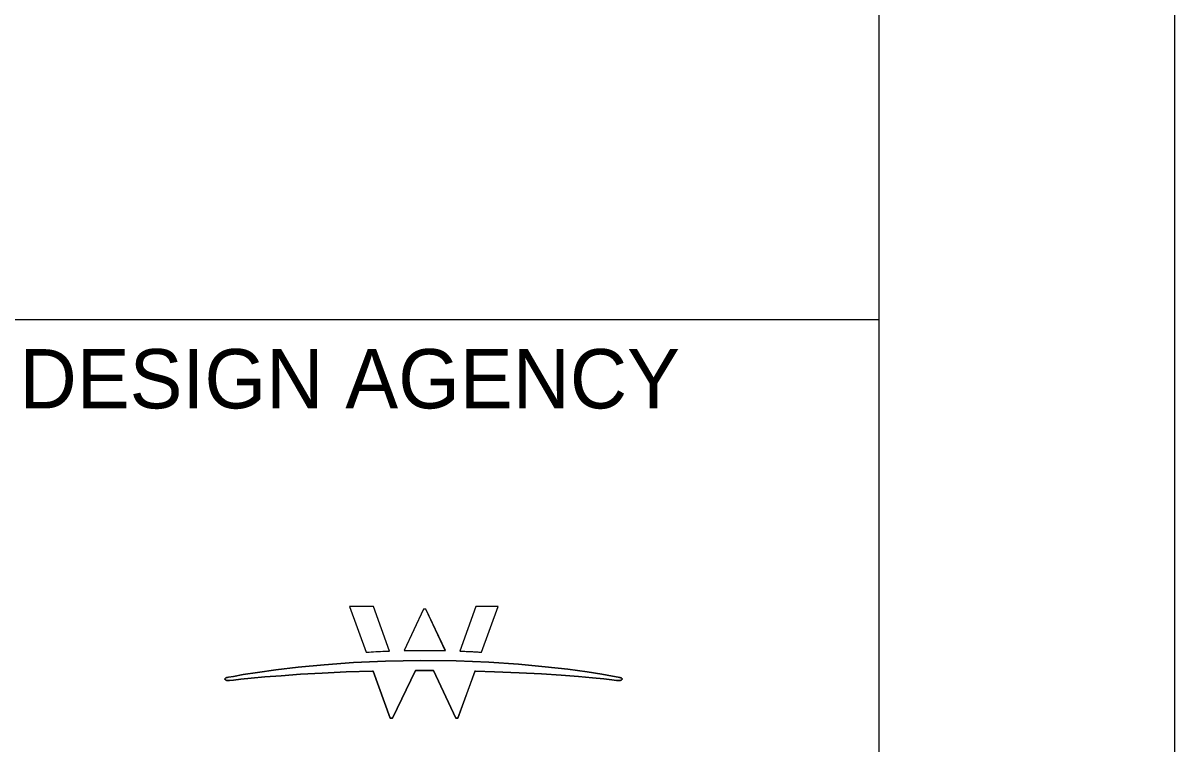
# Model space of a CAD drawing. Extents: x 0 to 1381193, y -3 to 468856.
# Drawn here: x 32.056 to 34, y 3.784 to 5 of the extents above; entities that cross this region are included whole.
import ezdxf

# ---------------------------------------------------------------- set-up
doc = ezdxf.new("R2010")
doc.units = 0
for name, color, linetype in [('SV_P_Mon_Cells_Set', 7, 'Continuous'), ('SV_X_Mon_Cells_Found', 7, 'Continuous'), ('SV_X_Shot_Marker', 7, 'Continuous')]:
    doc.layers.add(name, color=color, linetype=linetype)

msp = doc.modelspace()

# ---------------------------------------------------------------- linework, layer by layer
at = {"layer": 'SV_P_Mon_Cells_Set'}
msp.add_lwpolyline([(0, 0), (34, 0), (34, 22), (0, 22)], close=True, dxfattribs=at)
at = {"layer": 'SV_X_Mon_Cells_Found'}
msp.add_line((32, 4.5), (33.5, 4.5), dxfattribs=at)
msp.add_lwpolyline([(1.5, 21.5), (33.5, 21.5), (33.5, 0.5), (1.5, 0.5)], close=True, dxfattribs=at)
at = {"layer": 'SV_X_Shot_Marker'}
for points in [[(32.6475, 4.0156), (32.607, 4.0156), (32.6351, 3.9388), (32.6398, 3.9391), (32.6437, 3.9393), (32.6476, 3.9395), (32.6515, 3.9397), (32.6555, 3.9399), (32.6594, 3.9401), (32.6634, 3.9403), (32.6674, 3.9404), (32.6715, 3.9406), (32.6746, 3.9407)], [(32.7356, 4.0111), (32.7318, 4.0111), (32.6991, 3.9414), (32.6993, 3.9414), (32.701, 3.9415), (32.7028, 3.9415), (32.7045, 3.9415), (32.7063, 3.9415), (32.708, 3.9416), (32.7097, 3.9416), (32.7115, 3.9416), (32.7132, 3.9416), (32.715, 3.9417), (32.7168, 3.9417), (32.7185, 3.9417), (32.7203, 3.9417), (32.7221, 3.9417), (32.7239, 3.9417), (32.7256, 3.9417), (32.7274, 3.9418), (32.7292, 3.9418), (32.731, 3.9418), (32.7328, 3.9418), (32.7347, 3.9418), (32.7366, 3.9418), (32.7386, 3.9418), (32.7405, 3.9417), (32.7424, 3.9417), (32.7443, 3.9417), (32.7462, 3.9417), (32.7481, 3.9417), (32.7499, 3.9417), (32.7518, 3.9416), (32.7537, 3.9416), (32.7556, 3.9416), (32.7575, 3.9416), (32.7593, 3.9415), (32.7612, 3.9415), (32.763, 3.9415), (32.7649, 3.9414), (32.7667, 3.9414), (32.7686, 3.9414), (32.7689, 3.9414)], [(32.8202, 4.0156), (32.7933, 3.9406), (32.7943, 3.9406), (32.7961, 3.9405), (32.798, 3.9404), (32.7999, 3.9403), (32.8017, 3.9403), (32.8036, 3.9402), (32.8054, 3.9401), (32.8073, 3.94), (32.8091, 3.9399), (32.8109, 3.9399), (32.8127, 3.9398), (32.8146, 3.9397), (32.8164, 3.9396), (32.8182, 3.9395), (32.82, 3.9394), (32.8218, 3.9393), (32.8236, 3.9392), (32.8254, 3.9391), (32.8271, 3.939), (32.8298, 3.9388), (32.8575, 4.0156)]]:
    msp.add_lwpolyline(points, close=True, dxfattribs=at)
for points in [[(32.6475, 4.0156), (32.607, 4.0156), (32.6351, 3.9388), (32.6398, 3.9391), (32.6437, 3.9393), (32.6476, 3.9395), (32.6515, 3.9397), (32.6555, 3.9399), (32.6594, 3.9401), (32.6634, 3.9403), (32.6674, 3.9404), (32.6715, 3.9406), (32.6746, 3.9407), (32.6475, 4.0156)], [(32.7356, 4.0111), (32.7318, 4.0111), (32.6991, 3.9414), (32.701, 3.9415), (32.7028, 3.9415), (32.7045, 3.9415), (32.7063, 3.9415), (32.708, 3.9416), (32.7097, 3.9416), (32.7115, 3.9416), (32.7132, 3.9416), (32.715, 3.9417), (32.7168, 3.9417), (32.7185, 3.9417), (32.7203, 3.9417), (32.7221, 3.9417), (32.7239, 3.9417), (32.7256, 3.9417), (32.7274, 3.9418), (32.7292, 3.9418), (32.731, 3.9418), (32.7328, 3.9418), (32.7347, 3.9418), (32.7366, 3.9418), (32.7386, 3.9418), (32.7405, 3.9417), (32.7424, 3.9417), (32.7443, 3.9417), (32.7462, 3.9417), (32.7481, 3.9417), (32.7499, 3.9417), (32.7518, 3.9416), (32.7537, 3.9416), (32.7556, 3.9416), (32.7575, 3.9416), (32.7593, 3.9415), (32.7612, 3.9415), (32.763, 3.9415), (32.7649, 3.9414), (32.7667, 3.9414), (32.7686, 3.9414), (32.7356, 4.0111)], [(32.8202, 4.0156), (32.7933, 3.9406), (32.7943, 3.9406), (32.7961, 3.9405), (32.798, 3.9404), (32.7999, 3.9403), (32.8017, 3.9403), (32.8036, 3.9402), (32.8054, 3.9401), (32.8073, 3.94), (32.8091, 3.9399), (32.8109, 3.9399), (32.8127, 3.9398), (32.8146, 3.9397), (32.8164, 3.9396), (32.8182, 3.9395), (32.82, 3.9394), (32.8218, 3.9393), (32.8236, 3.9392), (32.8254, 3.9391), (32.8271, 3.939), (32.8298, 3.9388), (32.8575, 4.0156), (32.8202, 4.0156)], [(32.6457, 3.9069), (32.6012, 3.9055), (32.5605, 3.9036), (32.5239, 3.9015), (32.4915, 3.8992), (32.4638, 3.897), (32.441, 3.8949), (32.4233, 3.8931), (32.411, 3.8918), (32.4045, 3.891), (32.403, 3.8909), (32.402, 3.8909), (32.401, 3.891), (32.4001, 3.8911), (32.3993, 3.8913), (32.3985, 3.8916), (32.3979, 3.8919), (32.3973, 3.8923), (32.3969, 3.8927), (32.3967, 3.8931), (32.3966, 3.8936), (32.3967, 3.8941), (32.397, 3.8945), (32.3974, 3.8949), (32.3979, 3.8953), (32.3985, 3.8956), (32.3993, 3.8959), (32.4002, 3.8961), (32.4011, 3.8962), (32.4027, 3.8965), (32.4111, 3.898), (32.4275, 3.9009), (32.4515, 3.9047), (32.4826, 3.909), (32.5203, 3.9135), (32.564, 3.9177), (32.6134, 3.9212), (32.6679, 3.9237), (32.727, 3.9247), (32.7868, 3.924), (32.8421, 3.9217), (32.8923, 3.9184), (32.9369, 3.9143), (32.9755, 3.9099), (33.0077, 3.9055), (33.0328, 3.9016), (33.0505, 3.8985), (33.0603, 3.8966), (33.0625, 3.8962), (33.0635, 3.8961), (33.0643, 3.8958), (33.0651, 3.8956), (33.0657, 3.8952), (33.0663, 3.8949), (33.0667, 3.8945), (33.0669, 3.8941), (33.067, 3.8936), (33.0669, 3.8931), (33.0667, 3.8927), (33.0664, 3.8924), (33.0659, 3.892), (33.0654, 3.8917), (33.0648, 3.8915), (33.0641, 3.8912), (33.0633, 3.8911), (33.0625, 3.8909), (33.0616, 3.8909), (33.061, 3.8909), (33.0609, 3.8909), (33.0608, 3.8909), (33.0607, 3.8909), (33.0606, 3.8909), (33.0604, 3.8909), (33.0603, 3.8909), (33.0602, 3.8909), (33.0601, 3.8909), (33.06, 3.8909), (33.0577, 3.8912), (33.0497, 3.8921), (33.0361, 3.8936), (33.0172, 3.8955), (32.9932, 3.8976), (32.9643, 3.8999), (32.931, 3.9021), (32.8934, 3.9042), (32.8517, 3.9059), (32.8197, 3.9069), (32.8196, 3.9069), (32.8195, 3.9069), (32.8193, 3.9069), (32.8191, 3.9069), (32.8189, 3.9069), (32.8187, 3.9069), (32.8185, 3.9069), (32.8184, 3.9069), (32.7898, 3.8278), (32.7862, 3.8278), (32.7486, 3.908), (32.7485, 3.908), (32.7484, 3.908), (32.7481, 3.908), (32.7479, 3.908), (32.7476, 3.908), (32.7473, 3.908), (32.7471, 3.908), (32.7469, 3.908), (32.7468, 3.908), (32.7457, 3.908), (32.7442, 3.908), (32.7427, 3.908), (32.7413, 3.908), (32.74, 3.908), (32.7386, 3.908), (32.7372, 3.908), (32.7357, 3.908), (32.7342, 3.908), (32.7326, 3.908), (32.7311, 3.908), (32.7297, 3.908), (32.7284, 3.908), (32.7271, 3.908), (32.7258, 3.908), (32.7245, 3.908), (32.7232, 3.908), (32.7218, 3.908), (32.7204, 3.908), (32.7198, 3.908), (32.7197, 3.908), (32.7196, 3.908), (32.7194, 3.908), (32.7191, 3.908), (32.7189, 3.908), (32.7187, 3.908), (32.7185, 3.908), (32.7184, 3.908), (32.7184, 3.9079), (32.6795, 3.8278), (32.6757, 3.8278), (32.6467, 3.9069), (32.6467, 3.9069), (32.6466, 3.9069), (32.6464, 3.9069), (32.6463, 3.9069), (32.6461, 3.9069), (32.6459, 3.9069), (32.6458, 3.9069), (32.6457, 3.9069), (32.6457, 3.9069)], [(33.061, 3.8909), (33.0616, 3.8909), (33.0625, 3.8909), (33.0633, 3.8911), (33.0641, 3.8912), (33.0648, 3.8915), (33.0654, 3.8917), (33.0659, 3.892), (33.0664, 3.8924), (33.0667, 3.8927), (33.0669, 3.8931), (33.067, 3.8936), (33.0669, 3.8941), (33.0667, 3.8945), (33.0663, 3.8949), (33.0657, 3.8952), (33.0651, 3.8956), (33.0643, 3.8958), (33.0635, 3.8961), (33.0625, 3.8962), (33.0603, 3.8966), (33.0505, 3.8985), (33.0328, 3.9016), (33.0077, 3.9055), (32.9755, 3.9099), (32.9369, 3.9143), (32.8923, 3.9184), (32.8421, 3.9217), (32.7868, 3.924), (32.727, 3.9247), (32.6679, 3.9237), (32.6134, 3.9212), (32.564, 3.9177), (32.5203, 3.9135), (32.4826, 3.909), (32.4515, 3.9047), (32.4275, 3.9009), (32.4111, 3.898), (32.4027, 3.8965), (32.4011, 3.8962), (32.4002, 3.8961), (32.3993, 3.8959), (32.3985, 3.8956), (32.3979, 3.8953), (32.3974, 3.8949), (32.397, 3.8945), (32.3967, 3.8941), (32.3966, 3.8936), (32.3967, 3.8931), (32.3969, 3.8927), (32.3973, 3.8923), (32.3979, 3.8919), (32.3985, 3.8916), (32.3993, 3.8913), (32.4001, 3.8911), (32.401, 3.891), (32.402, 3.8909), (32.403, 3.8909), (32.4045, 3.891), (32.411, 3.8918), (32.4233, 3.8931), (32.441, 3.8949), (32.4638, 3.897), (32.4915, 3.8992), (32.5239, 3.9015), (32.5605, 3.9036), (32.6012, 3.9055), (32.6457, 3.9069), (32.6464, 3.9069)], [(32.6467, 3.9069), (32.6757, 3.8278), (32.6795, 3.8278), (32.7185, 3.908), (32.7189, 3.908), (32.7194, 3.908), (32.7198, 3.908), (32.7204, 3.908), (32.7218, 3.908), (32.7232, 3.908), (32.7245, 3.908), (32.7258, 3.908), (32.7271, 3.908), (32.7284, 3.908), (32.7297, 3.908), (32.7311, 3.908), (32.7326, 3.908), (32.7342, 3.908), (32.7357, 3.908), (32.7372, 3.908), (32.7386, 3.908), (32.74, 3.908), (32.7413, 3.908), (32.7427, 3.908), (32.7442, 3.908), (32.7457, 3.908), (32.7471, 3.908), (32.7476, 3.908), (32.7481, 3.908), (32.7486, 3.908), (32.7862, 3.8278), (32.7898, 3.8278), (32.8187, 3.9069), (32.8191, 3.9069), (32.8196, 3.9069)], [(32.6464, 3.9069), (32.6467, 3.9069)], [(32.8196, 3.9069), (32.8197, 3.9069)], [(32.8197, 3.9069), (32.8517, 3.9059), (32.8934, 3.9042), (32.931, 3.9021), (32.9643, 3.8999), (32.9932, 3.8976), (33.0172, 3.8955), (33.0361, 3.8936), (33.0497, 3.8921), (33.0577, 3.8912), (33.0602, 3.8909), (33.0606, 3.8909), (33.0609, 3.8909)], [(33.0609, 3.8909), (33.061, 3.8909)]]:
    msp.add_lwpolyline(points, dxfattribs=at)

# ---------------------------------------------------------------- texts
msp.add_text('DESIGN AGENCY', height=0.1, dxfattribs=at).set_placement((32.05, 4.35))

doc.saveas('drawing.dxf')
